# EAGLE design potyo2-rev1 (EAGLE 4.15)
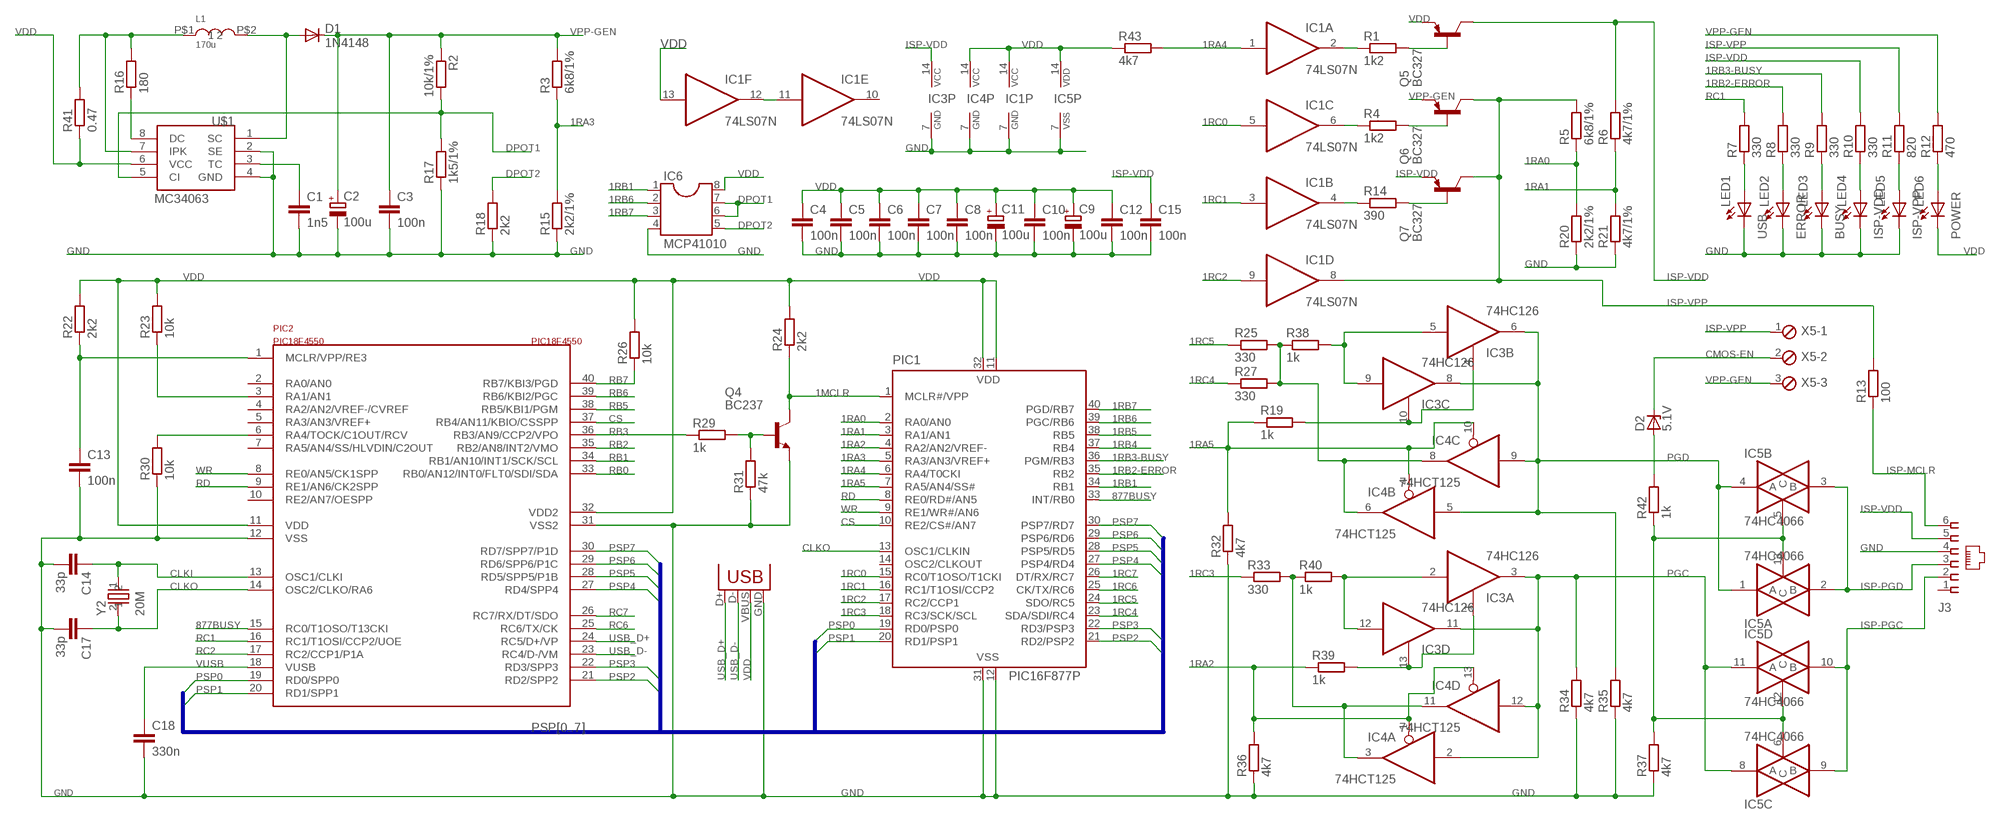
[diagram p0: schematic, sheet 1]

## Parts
C1  1n5  C-EU050-024X044  [C050-024X044]
C2  100u  CPOL-EUE2.5-7  [E2,5-7]
C3  100n  C-EU050-024X044  [C050-024X044]
C4  100n  C-EU050-024X044  [C050-024X044]
C5  100n  C-EU050-024X044  [C050-024X044]
C6  100n  C-EU050-024X044  [C050-024X044]
C7  100n  C-EU050-024X044  [C050-024X044]
C8  100n  C-EU050-024X044  [C050-024X044]
C9  100u  CPOL-EUE2.5-7  [E2,5-7]
C10  100n  C-EU050-024X044  [C050-024X044]
C11  100u  CPOL-EUE2.5-7  [E2,5-7]
C12  100n  C-EU050-024X044  [C050-024X044]
C13  100n  C-EU050-024X044  [C050-024X044]
C14  33p  C-EU050-024X044  [C050-024X044]
C15  100n  C-EU050-024X044  [C050-024X044]
C17  33p  C-EU050-024X044  [C050-024X044]
C18  330n  C-EU050-024X044  [C050-024X044]
D1  1N4148  1N4148DO35-7  [DO35-7]
D2  5.1V  ZENER-DIODEDO34-7  [DO34Z7]
IC1  74LS07N  [DIL14]
IC3  74HC126  74HC126N  [DIL14]
IC4  74HCT125  74HC125N  [DIL14]
IC5  74HC4066  4066N  [DIL14]
IC6  MCP41010  DIL8  [DIL08]
J3  520250-3  [520250-3]
L1  170u  RFB0810  [RFB0810]
LED1  USB  LED5MM  [LED5MM]
LED2  ERROR  LED5MM  [LED5MM]
LED3  BUSY  LED5MM  [LED5MM]
LED4  ISP-VDD  LED5MM  [LED5MM]
LED5  ISP-VPP  LED5MM  [LED5MM]
LED6  POWER  LED5MM  [LED5MM]
PIC1  PIC16F877P  PIC16F8777P  [DIL40]
PIC2  PIC18F4550  [PDIP-40]
Q4  BC237  BC337  [TO92]
Q5  BC327  [TO92-EBC]
Q6  BC327  [TO92-EBC]
Q7  BC327  [TO92-EBC]
R1  1k2  R-EU_0207/10  [0207/10]
R2  10k/1%  R-EU_0207/10  [0207/10]
R3  6k8/1%  R-EU_0207/10  [0207/10]
R4  1k2  R-EU_0207/10  [0207/10]
R5  6k8/1%  R-EU_0207/10  [0207/10]
R6  4k7/1%  R-EU_0207/10  [0207/10]
R7  330  R-EU_0207/10  [0207/10]
R8  330  R-EU_0207/10  [0207/10]
R9  330  R-EU_0207/10  [0207/10]
R10  330  R-EU_0207/10  [0207/10]
R11  820  R-EU_0207/10  [0207/10]
R12  470  R-EU_0207/10  [0207/10]
R13  100  R-EU_0207/10  [0207/10]
R14  390  R-EU_0207/10  [0207/10]
R15  2k2/1%  R-EU_0207/10  [0207/10]
R16  180  R-EU_0207/10  [0207/10]
R17  1k5/1%  R-EU_0207/10  [0207/10]
R18  2k2  R-EU_0207/10  [0207/10]
R19  1k  R-EU_0207/10  [0207/10]
R20  2k2/1%  R-EU_0207/10  [0207/10]
R21  4k7/1%  R-EU_0207/10  [0207/10]
R22  2k2  R-EU_0207/10  [0207/10]
R23  10k  R-EU_0207/10  [0207/10]
R24  2k2  R-EU_0207/10  [0207/10]
R25  330  R-EU_0207/10  [0207/10]
R26  10k  R-EU_0207/10  [0207/10]
R27  330  R-EU_0207/10  [0207/10]
R29  1k  R-EU_0207/10  [0207/10]
R30  10k  R-EU_0207/10  [0207/10]
R31  47k  R-EU_0207/10  [0207/10]
R32  4k7  R-EU_0207/10  [0207/10]
R33  330  R-EU_0207/10  [0207/10]
R34  4k7  R-EU_0207/10  [0207/10]
R35  4k7  R-EU_0207/10  [0207/10]
R36  4k7  R-EU_0207/10  [0207/10]
R37  4k7  R-EU_0207/10  [0207/10]
R38  1k  R-EU_0207/10  [0207/10]
R39  1k  R-EU_0207/10  [0207/10]
R40  1k  R-EU_0207/10  [0207/10]
R41  0.47  R-EU_0207/10  [0207/10]
R42  1k  R-EU_0207/10  [0207/10]
R43  4k7  R-EU_0207/10  [0207/10]
U$1  MC34063  [DIL08]
X1  USB-B-H  [USB-B-H]
X5  MPT3  [3POL254]
Y2  20M  QUARTZ  [QUARTZ]

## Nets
1MCLR: PIC1.1(MCLR#/VPP) Q4.3(C) R24.1
1RA0: PIC1.2(RA0/AN0) R5.1 R20.2
1RA1: PIC1.3(RA1/AN1) R6.1 R21.2
1RA2: IC4.1(A:OE) IC4.13(D:OE) PIC1.4(RA2/AN2/VREF-) R36.2 R39.1
1RA3: PIC1.5(RA3/AN3/VREF+) R3.1 R15.2
1RA4: IC1.1(A:I) PIC1.6(RA4/T0CKI) R43.2
1RA5: IC4.4(B:OE) IC4.10(C:OE) PIC1.7(RA5/AN4/SS#) R19.1 R32.2
1RB1: IC6.1 PIC1.34(RB1)
1RB2-ERROR: PIC1.35(RB2) R8.2
1RB3-BUSY: PIC1.36(PGM/RB3) R9.2
1RB4: PIC1.37(RB4)
1RB5: PIC1.38(RB5)
1RB6: IC6.2 PIC1.39(PGC/RB6)
1RB7: IC6.3 PIC1.40(PGD/RB7)
1RC0: IC1.5(C:I) PIC1.15(RC0/T1OSO/T1CKI)
1RC1: IC1.3(B:I) PIC1.16(RC1/T1OSI/CCP2)
1RC2: IC1.9(D:I) PIC1.17(RC2/CCP1)
1RC3: PIC1.18(RC3/SCK/SCL) R33.1
1RC4: PIC1.23(SDA/SDI/RC4) R27.1
1RC5: PIC1.24(SDO/RC5) R25.1
1RC6: PIC1.25(CK/TX/RC6)
1RC7: PIC1.26(DT/RX/RC7)
877BUSY: PIC1.33(INT/RB0) PIC2.15(RC0/T1OSO/T13CKI)
CLKI: C14.1 PIC2.13(OSC1/CLKI) Y2.1
CLKO: C17.1 PIC1.13(OSC1/CLKIN) PIC2.14(OSC2/CLKO/RA6) Y2.2
CMOS-EN: D2.C X5.2
CMOS-EN2: IC5.5(B:C) IC5.6(C:C) IC5.12(D:C) IC5.13(A:C) R37.2 R42.1
CS: PIC1.10(RE2/CS#/AN7) PIC2.37(RB4/AN11/KBIO/CSSPP)
DPOT1: IC6.6 IC6.7 R2.2 R17.2 U$1.5(CI)
DPOT2: IC6.5 R18.2
GND: C1.2 C2.- C3.2 C4.2 C5.2 C6.2 C7.2 C8.2 C9.- C10.2 C11.- C12.2 C13.2 C14.2 C15.2 C17.2 C18.2 IC1.7(P:GND) IC3.7(P:GND) IC4.7(P:GND) IC5.7(P:VSS) IC6.4 J3.4 LED1.K(C) LED2.K(C) LED3.K(C) LED4.K(C) LED5.K(C) PIC1.12(VSS) PIC1.31(VSS) PIC2.12(VSS) PIC2.31(VSS2) Q4.1(E) R15.1 R17.1 R18.1 R20.1 R21.1 R30.1 R31.1 R32.1 R34.1 R35.1 R36.1 R37.1 U$1.2(SE) U$1.4(GND) X1.GND
ISP-MCLR: J3.6 R13.1
ISP-PGC: IC5.9(C:B) IC5.10(D:B) J3.2
ISP-PGD: IC5.2(A:B) IC5.3(B:B) J3.3
ISP-VDD: C15.1 IC3.14(P:VCC) J3.5 Q5.C Q7.E R6.2 R10.2
ISP-VPP: IC1.8(D:O) Q6.C Q7.C R5.2 R11.2 R13.2 X5.1
MCLR: C13.1 PIC2.1(MCLR/VPP/RE3) R22.1
N$1: IC3.4(B:OE) IC3.10(C:OE) R19.2
N$2: IC3.5(B:I) IC3.9(C:I) R38.2
N$3: R16.1 U$1.8(DC)
N$4: D2.A R42.2
N$5: LED1.A R7.1
N$8: PIC2.6(RA4/TOCK/C1OUT/RCV) R30.2
N$9: PIC2.3(RA1/AN1) R23.1
N$10: Q4.2(B) R29.2 R31.2
N$12: D1.A L1.P$2 U$1.1(SC)
N$13: LED2.A R8.1
N$14: LED3.A R9.1
N$15: IC1.2(A:O) R1.1
N$16: IC1.6(C:O) R4.1
N$17: IC1.4(B:O) R14.1
N$18: Q5.B R1.2
N$19: Q6.B R4.2
N$20: IC3.2(A:I) IC3.12(D:I) R40.2
N$21: Q7.B R14.2
N$22: IC4.6(B:O) IC4.8(C:O) R25.2 R27.2 R38.1
N$23: IC3.1(A:OE) IC3.13(D:OE) R39.2
N$24: C1.1 U$1.3(TC)
N$25: L1.P$1 R16.2 R41.2 U$1.7(IPK)
N$27: LED4.A R10.1
N$28: IC4.3(A:O) IC4.11(D:O) R33.2 R40.1
N$29: LED5.A R11.1
N$30: LED6.A R12.1
N$31: IC1.11(E:I) IC1.12(F:O)
PGC: IC3.3(A:O) IC3.11(D:O) IC4.2(A:I) IC4.12(D:I) IC5.8(C:A) IC5.11(D:A) R34.2
PGD: IC3.6(B:O) IC3.8(C:O) IC4.5(B:I) IC4.9(C:I) IC5.1(A:A) IC5.4(B:A) R35.2
PSP0: PIC1.19(RD0/PSP0) PIC2.19(RD0/SPP0)
PSP1: PIC1.20(RD1/PSP1) PIC2.20(RD1/SPP1)
PSP2: PIC1.21(RD2/PSP2) PIC2.21(RD2/SPP2)
PSP3: PIC1.22(RD3/PSP3) PIC2.22(RD3/SPP3)
PSP4: PIC1.27(PSP4/RD4) PIC2.27(RD4/SPP4)
PSP5: PIC1.28(PSP5/RD5) PIC2.28(RD5/SPP5/P1B)
PSP6: PIC1.29(PSP6/RD6) PIC2.29(RD6/SPP6/P1C)
PSP7: PIC1.30(PSP7/RD7) PIC2.30(RD7/SPP7/P1D)
RB0: PIC2.33(RB0/AN12/INT0/FLT0/SDI/SDA)
RB1: PIC2.34(RB1/AN10/INT1/SCK/SCL)
RB2: PIC2.35(RB2/AN8/INT2/VMO)
RB3: PIC2.36(RB3/AN9/CCP2/VPO) R29.1
RB5: PIC2.38(RB5/KBI1/PGM)
RB6: PIC2.39(RB6/KBI2/PGC)
RB7: PIC2.40(RB7/KBI3/PGD) R26.1
RC1: PIC2.16(RC1/T1OSI/CCP2/UOE) R7.2
RC2: PIC2.17(RC2/CCP1/P1A)
RC6: PIC2.25(RC6/TX/CK)
RC7: PIC2.26(RC7/RX/DT/SDO)
RD: PIC1.8(RE0/RD#/AN5) PIC2.9(RE1/AN6/CK2SPP)
USB_D+: PIC2.24(RC5/D+/VP) X1.D+
USB_D-: PIC2.23(RC4/D-/VM) X1.D-
VDD: C4.1 C5.1 C6.1 C7.1 C8.1 C9.+ C10.1 C11.+ C12.1 IC1.13(F:I) IC1.14(P:VCC) IC4.14(P:VCC) IC5.14(P:VDD) IC6.8 LED6.K(C) PIC1.11(VDD) PIC1.32(VDD) PIC2.11(VDD) PIC2.32(VDD2) Q5.E R22.2 R23.2 R24.2 R26.2 R41.1 R43.1 U$1.6(VCC) X1.VBUS
VPP-GEN: C2.+ C3.1 D1.C Q6.E R2.1 R3.2 R12.2 X5.3
VUSB: C18.1 PIC2.18(VUSB)
WR: PIC1.9(RE1/WR#/AN6) PIC2.8(RE0/AN5/CK1SPP)
Unconnected: IC1.10(E:O) J3.1 PIC1.14(OSC2/CLKOUT) PIC2.2(RA0/AN0) PIC2.4(RA2/AN2/VREF-/CVREF) PIC2.5(RA3/AN3/VREF+) PIC2.7(RA5/AN4/SS/HLVDIN/C2OUT) PIC2.10(RE2/AN7/OESPP)

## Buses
PSP[0..7]

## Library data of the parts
C1 C3-C8 C10 C12-C15 C17 C18 = sajat:C-EU: CAPACITOR, European symbol
C2 C9 C11 = sajat:CPOL-EU: POLARIZED CAPACITOR, European symbol
D1 = sajat:1N4148: DIODE
D2 = diode:ZENER-DIODE: Z-Diode
IC1 = sajat:74*07: Hex BUFFER, open collector high-voltage output
IC3 = sajat:74*126: Quad bus BUFFER, 3-state
IC4 = sajat:74*125: Quad bus BUFFER, 3-state
IC5 = sajat:4066: Quad bilateral ANALOG SWITCH
IC6 = ic-package:DIL8: Dual In Line
J3 = sajat:520250-3: AMP connector
L1 = sajat:RFB0810
LED1-LED6 = sajat:LED: LED
PIC1 = sajat:PIC16F877: MICROCONTROLLER
PIC2 = pic18f4550:PIC18F4550
Q4 = sajat:BC337*: NPN Transistor
Q5-Q7 = sajat:BC327*: PNP Transistror
R1-R27 R29-R43 = sajat:R-EU_: RESISTOR, European symbol
U$1 = sajat:MC34063
X1 = sajat:USB: USB Connectors
X5 = sajat:MPT3: PHOENIX CONNECTOR
Y2 = sajat:QUARTZ

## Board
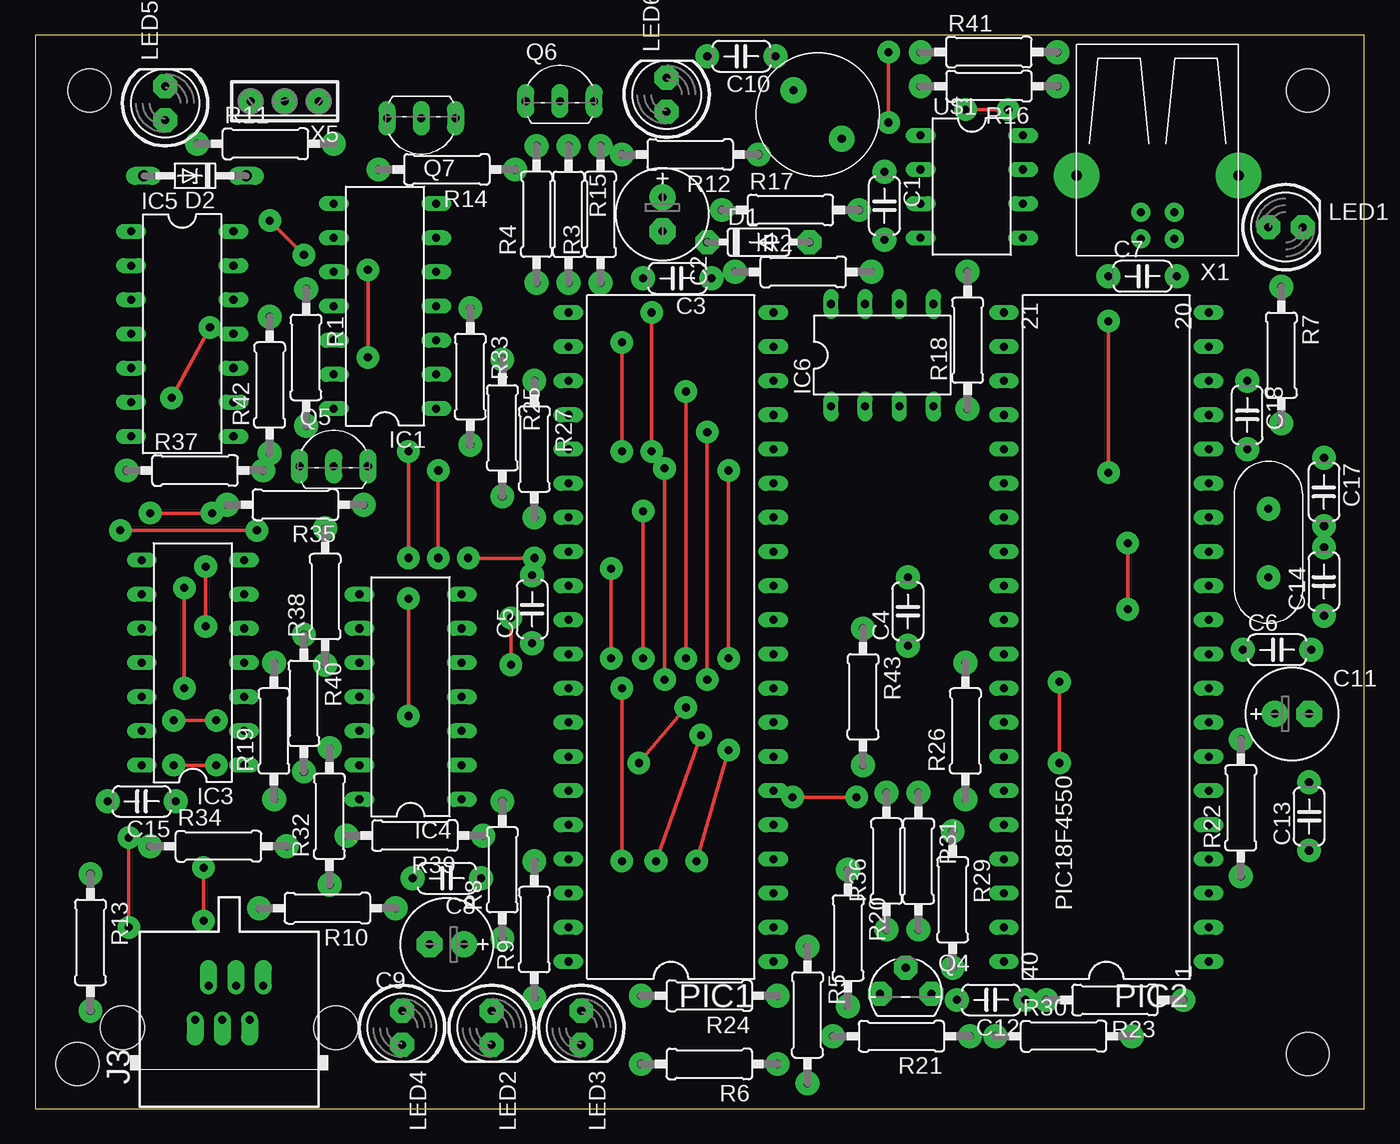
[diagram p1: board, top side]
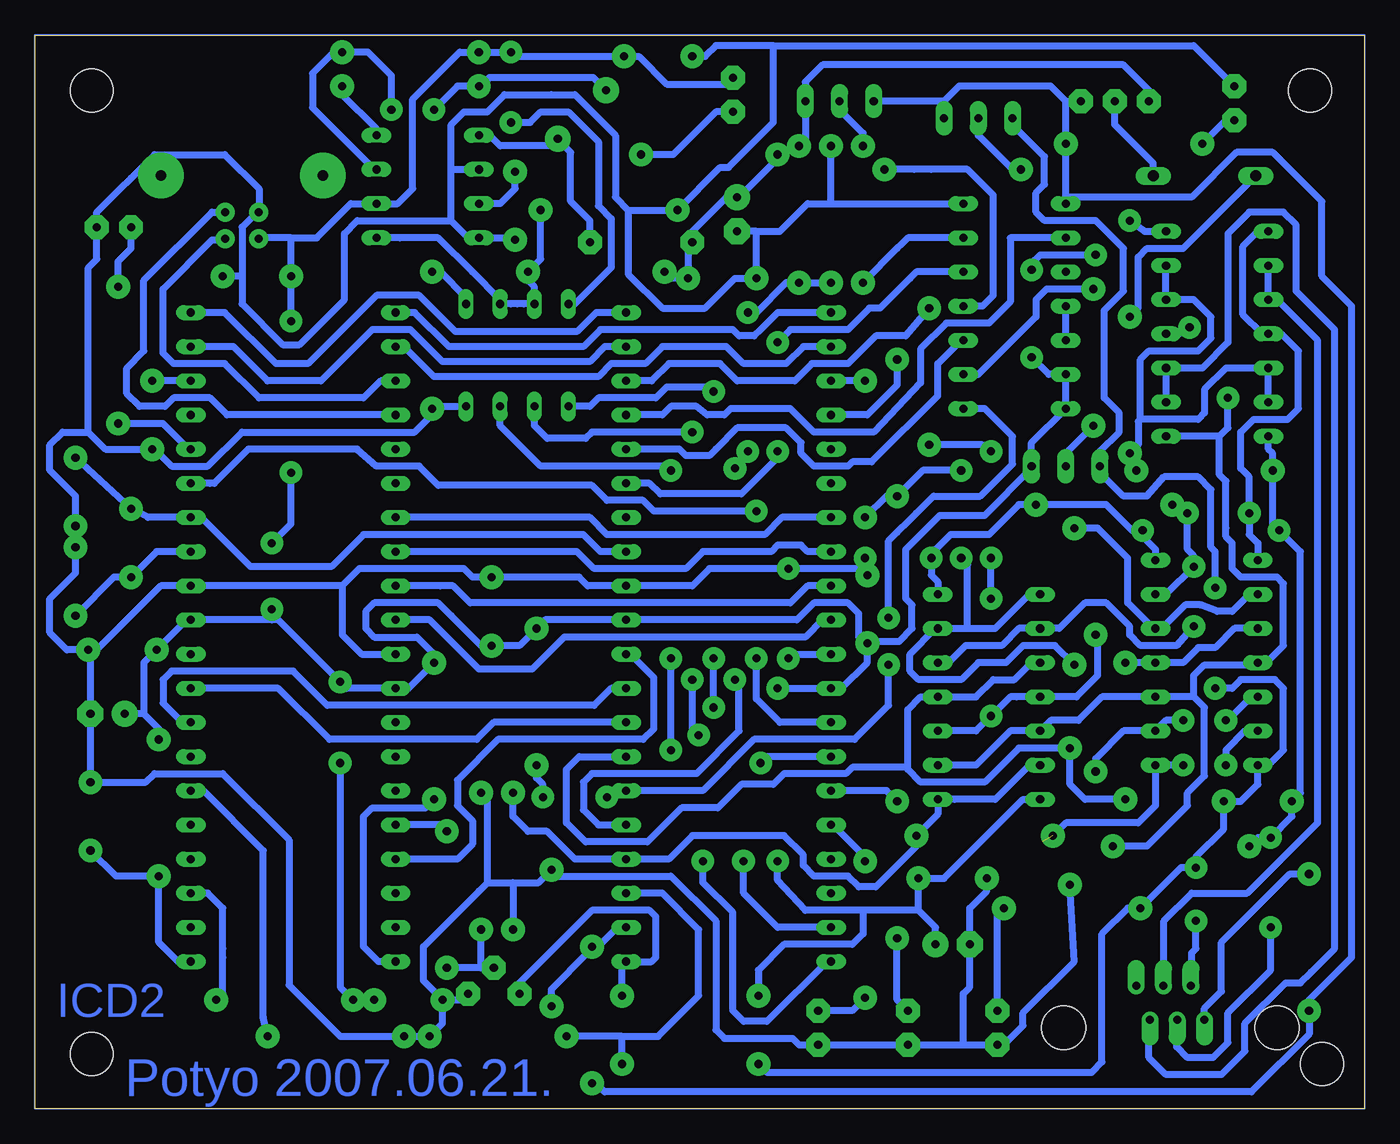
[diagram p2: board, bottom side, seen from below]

Size 98.88 x 79.84 mm. Coordinates in mm from the lower left corner, seen from the top.
Outline: 0,0 98.88,0 98.88,79.84 0,79.84 0,0
Copper layers (1*16): Top 0.035mm / dielectric 1.5mm / Bottom 0.035mm
Design rules "default": minimum track width 20mil, minimum drill 10mil, track to track 10mil, track to pad 10mil, pad to pad 10mil, via to via 10mil, smd to smd 8mil, copper to edge 10mil, drill to drill 15mil, minimum pad ring 10mil, minimum via ring 8mil, stop-mask expansion 4mil, vias tented up to drill 0mil, thermal gap 10mil
Holes 3.2 mm at 4.06,75.72 94.67,75.72 94.67,4.06 3.17,3.33

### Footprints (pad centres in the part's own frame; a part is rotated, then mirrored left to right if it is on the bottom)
C050-024X044 = drill 0.6 pad 1.778 round: 1 -2.54,0; 2 2.54,0
E2,5-7 = drill 0.6 pad 1.93 round: + -1.27,0 | drill 0.6 pad 1.93 octagon: - 1.27,0
DO35-7 = drill 0.6 pad 1.778 octagon: A 3.81,0; C -3.81,0
DO34Z7 = drill 0.813 long: A 3.81,0; C -3.81,0
DIL14 = drill 0.6 pad 1.016 long: 1 -7.62,-3.81; 2 -5.08,-3.81; 3 -2.54,-3.81; 4 0,-3.81; 5 2.54,-3.81; 6 5.08,-3.81; 7 7.62,-3.81; 8 7.62,3.81; 9 5.08,3.81; 10 2.54,3.81; 11 0,3.81; 12 -2.54,3.81; 13 -5.08,3.81; 14 -7.62,3.81
DIL08 = drill 0.6 pad 1.016 long: 1 -3.81,-3.81; 2 -1.27,-3.81; 3 1.27,-3.81; 4 3.81,-3.81; 5 3.81,3.81; 6 1.27,3.81; 7 -1.27,3.81; 8 -3.81,3.81
520250-3 = drill 0.6 pad 1.27 offset: 1 2.54,3.118; 2 1.524,0.578; 3 0.508,3.118; 4 -0.508,0.578; 5 -1.524,3.118; 6 -2.54,0.578 | hole 3.251: -7.938,0; 7.938,0
RFB0810 = drill 0.6 pad 1.93 round: P$1 -2.54,0; P$2 2.54,0
LED5MM = drill 0.6 pad 1.778 octagon: A -1.27,0; K 1.27,0
DIL40 = drill 0.6 pad 1.016 long: 1 -24.13,-7.62; 2 -21.59,-7.62; 3 -19.05,-7.62; 4 -16.51,-7.62; 5 -13.97,-7.62; 6 -11.43,-7.62; 7 -8.89,-7.62; 8 -6.35,-7.62; 9 -3.81,-7.62; 10 -1.27,-7.62; 11 1.27,-7.62; 12 3.81,-7.62; 13 6.35,-7.62; 14 8.89,-7.62; 15 11.43,-7.62; 16 13.97,-7.62; 17 16.51,-7.62; 18 19.05,-7.62; 19 21.59,-7.62; 20 24.13,-7.62; 21 24.13,7.62; 22 21.59,7.62; 23 19.05,7.62; 24 16.51,7.62; 25 13.97,7.62; 26 11.43,7.62; 27 8.89,7.62; 28 6.35,7.62; 29 3.81,7.62; 30 1.27,7.62; 31 -1.27,7.62; 32 -3.81,7.62; 33 -6.35,7.62; 34 -8.89,7.62; 35 -11.43,7.62; 36 -13.97,7.62; 37 -16.51,7.62; 38 -19.05,7.62; 39 -21.59,7.62; 40 -24.13,7.62
PDIP-40 = drill 0.6 pad 1.016 long: 1 -19.05,-8.89; 2 -16.51,-8.89; 3 -13.97,-8.89; 4 -11.43,-8.89; 5 -8.89,-8.89; 6 -6.35,-8.89; 7 -3.81,-8.89; 8 -1.27,-8.89; 9 1.27,-8.89; 10 3.81,-8.89; 11 6.35,-8.89; 12 8.89,-8.89; 13 11.43,-8.89; 14 13.97,-8.89; 15 16.51,-8.89; 16 19.05,-8.89; 17 21.59,-8.89; 18 24.13,-8.89; 19 26.67,-8.89; 20 29.21,-8.89; 21 29.21,6.35; 22 26.67,6.35; 23 24.13,6.35; 24 21.59,6.35; 25 19.05,6.35; 26 16.51,6.35; 27 13.97,6.35; 28 11.43,6.35; 29 8.89,6.35; 30 6.35,6.35; 31 3.81,6.35; 32 1.27,6.35; 33 -1.27,6.35; 34 -3.81,6.35; 35 -6.35,6.35; 36 -8.89,6.35; 37 -11.43,6.35; 38 -13.97,6.35; 39 -16.51,6.35; 40 -19.05,6.35
TO92 = drill 0.6 pad 1.778 octagon: 1 1.905,0; 2 0,1.905; 3 -1.905,0
TO92-EBC = drill 0.6 pad 1.27 long: B 0,-1.27; C -2.54,-1.27; E 2.54,-1.27
0207/10 = drill 0.6 pad 1.778 round: 1 -5.08,0; 2 5.08,0
USB-B-H = drill 0.6 pad 1.422 round: D+ 0,1.25; D- 1.981,1.25; GND 0,-1.25; VBUS 1.981,-1.25 | drill 0.8 pad 3.4 round: P$1 -2.718,-6.02; P$2 -2.718,6.02
3POL254 = drill 0.6 pad 1.778 octagon: 1 -2.54,0; 2 0,0; 3 2.54,0
QUARTZ = drill 0.6 pad 1.778 round: 1 -2.54,0; 2 2.54,0

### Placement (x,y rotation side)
C1  63.18,67.15 270 top
C2  46.67,66.51 270 top
C3  47.78,61.75 180 top
C4  64.92,36.98 90 top
C5  36.98,37.14 90 top
C6  92.39,34.12 0 top
C7  82.39,61.91 0 top
C8  30.63,17.14 180 top
C9  30.63,12.22 180 top
C10  52.54,78.26 180 top
C11  93.5,29.36 0 top
C12  71.12,8.09 180 top
C13  94.77,21.74 90 top
C14  95.88,39.2 90 top
C15  7.93,22.85 180 top
C17  95.88,45.87 270 top
C18  90.16,51.59 270 top
D1  53.81,64.45 0 top
D2  11.9,69.37 180 top
IC1  26.03,59.68 90 top
IC3  11.74,33.17 90 top
IC4  27.93,30.63 90 top
IC5  10.95,57.62 270 top
IC6  63.02,56.03 0 top
J3  14.44,6.03 0 top
L1  58.21,73.92 315 top
LED1  93.02,65.56 0 top
LED2  33.97,6.03 270 top
LED3  40.63,6.03 270 top
LED4  27.3,6.03 270 top
LED5  9.68,74.77 90 top
LED6  46.99,75.4 90 top
PIC1  47.3,35.08 90 top
PIC2  78.42,30 90 top
Q4  64.77,8.57 0 top
Q5  22.22,49.05 0 top
Q6  39.05,76.19 0 top
Q7  28.73,72.38 180 top
R1  20.16,55.87 270 top
R2  57.15,62.22 0 top
R3  42.06,66.51 90 top
R4  37.3,66.51 90 top
R5  57.46,6.98 270 top
R6  50.16,3.33 180 top
R7  92.7,56.03 270 top
R8  34.76,17.77 90 top
R9  37.14,13.33 90 top
R10  21.74,14.92 180 top
R11  17.14,71.75 0 top
R12  48.73,70.95 180 top
R13  4.12,12.38 270 top
R14  30.63,69.84 180 top
R15  39.68,66.51 270 top
R16  70.96,76.04 180 top
R17  56.19,66.83 0 top
R18  69.37,57.14 90 top
R19  17.77,28.09 90 top
R20  60.48,12.69 270 top
R21  64.45,5.39 180 top
R22  89.69,22.38 90 top
R23  80.32,8.09 180 top
R24  50.16,8.41 180 top
R25  34.76,50.63 270 top
R26  69.21,28.09 90 top
R27  37.14,49.05 270 top
R29  68.26,15.55 270 top
R30  76.51,5.39 0 top
R31  65.72,18.41 270 top
R32  21.9,21.74 90 top
R33  32.38,54.44 270 top
R34  13.65,19.52 0 top
R35  19.36,44.92 180 top
R36  63.34,18.41 90 top
R37  11.9,47.46 0 top
R38  21.59,38.09 90 top
R39  28.25,20.31 180 top
R40  20,30.16 270 top
R41  70.96,78.57 0 top
R42  17.46,53.81 90 top
R43  61.59,30.63 270 top
U$1  69.69,68.57 270 top
X1  83.5,66.67 270 top
X5  18.57,74.92 180 top
Y2  91.75,42.06 90 top

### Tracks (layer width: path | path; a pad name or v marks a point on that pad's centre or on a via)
1MCLR
  Bottom 0.508: PIC1.1 55.24,10.63 R24.1 | R24.1 | PIC1.1 | PIC1.1 53.02,10.95 52.7,11.26 52.7,14.28 53.18,14.76 57.46,14.76 62.86,9.36 Q4.3 | Q4.3
1RA0
  Bottom 0.508: 57.46,11.58 | 57.46,11.58 R5.1 | PIC1.2 55.56,13.49 57.46,11.58 | R20.2 60.48,8.88 57.78,11.58 57.46,11.58
1RA1
  Bottom 0.508: PIC1.3 52.22,16.03 49.52,13.33 49.52,8.41 52.54,5.39 55.4,5.39 | R6.1 | 55.24,5.39 55.4,5.39 | 55.4,5.39 R21.2 | R6.1 55.24,5.39 | 55.24,5.39 | 55.4,5.39
1RA2
  Bottom 0.508: IC4.13 24.92,25.55 27.46,23.01 | 27.46,23.01 30.47,23.01 | 30.47,23.01 IC4.1 | IC4.13 | 27.46,23.01 | 30.47,23.01 | IC4.1 | R36.2 | R36.2 63.34,21.74 62.22,20.63 60.8,20.63 58.73,18.57 PIC1.4 51.75,18.57 50,20.31 43.17,20.31 41.75,18.88 41.75,18.09 40.95,17.3 38.41,17.3 37.62,16.5 36.35,16.5 33.33,19.52 R39.1 | R39.1 | IC4.1 31.74,21.9 R39.1
1RA3  (via drill 0.6 pad 1.68)
  Top 0.254: v45.87,48.89 v45.87,59.21 | v46.83,31.9 v46.83,47.62
  Bottom 0.508: PIC1.5 56.99,21.11 58.1,22.22 58.1,24.28 57.46,24.92 53.02,24.92 | v46.83,31.9 46.51,31.58 46.51,28.09 49.68,24.92 53.02,24.92 | R15.2 | R15.2 R3.1 43.02,61.43 45.24,59.21 | 53.02,24.92 | 45.24,59.21 | v45.87,59.21 45.24,59.21 | v46.83,47.62 46.83,47.3 | v46.83,47.62 | v45.87,48.89 45.87,48.57 v46.83,47.62
1RA4  (via drill 0.6 pad 1.68)
  Top 0.254: v35.4,33.01 v35.4,36.51 | v56.35,23.17 v61.11,23.17
  Bottom 0.508: v35.4,36.51 35.4,36.66 35.4,42.22 34.76,42.86 33.81,43.81 33.33,44.28 | IC1.1 | IC1.1 28.25,52.06 26.19,50 26.19,47.94 28.57,45.55 32.06,45.55 33.33,44.28 | 33.33,44.28 | v35.4,33.01 35.4,30 37.94,27.46 45.4,27.46 49.21,23.65 49.52,23.65 PIC1.6 v56.35,23.17 | v61.11,23.17 61.11,24.12 61.59,24.6 R43.2 | R43.2
1RA5
  Bottom 0.508: PIC1.7 58.41,26.19 59.37,25.23 59.37,21.27 57.94,19.84 53.33,19.84 50.79,22.38 48.1,22.38 46.35,24.12 43.97,24.12 43.17,24.92 38.57,24.92 38.09,25.39 33.97,25.39 | IC4.10 | IC4.10 24.76,33.17 26.03,31.9 27.62,31.9 28.89,30.63 IC4.4 | IC4.4 | IC4.4 33.01,30.63 33.97,29.68 33.97,25.39 | 33.97,25.39 33.97,25.23 33.01,24.28 28.25,24.28 25.71,26.82 R32.2 | 17.62,23.01 R19.1 20.79,23.01 21.9,24.12 R32.2 | R32.2 | R32.2 | R32.2 | R32.2
1RB1  (via drill 0.6 pad 1.68)
  Top 0.254: v44.92,25.71 v48.41,29.84 | v48.41,33.49 v48.41,53.33
  Bottom 0.508: v48.41,29.84 v48.41,33.49 | IC6.1 57.62,52.22 57.3,52.54 56.99,52.86 52.7,52.86 51.91,53.65 48.73,53.65 v48.41,53.33 | v44.92,25.71 | PIC1.34 44.44,26.19 v44.92,25.71
1RB2-ERROR
  Bottom 0.508: R8.2 35.55,23.65 PIC1.35
1RB3-BUSY
  Bottom 0.508: PIC1.36 39.52,21.11 37.14,18.73 R9.2
1RB6  (via drill 0.6 pad 1.68)
  Top 0.254: v46.19,18.41 v49.52,27.77 | v50,31.9 v50,50.32
  Bottom 0.508: v49.52,27.77 50,28.25 v50,31.9 | v50,50.32 57.46,50.32 57.94,49.84 60.8,49.84 61.75,50.79 IC6.2 | PIC1.39 43.65,13.49 46.19,16.03 v46.19,18.41
1RB7  (via drill 0.6 pad 1.68)
  Top 0.254: v49.21,18.41 v51.59,26.66 | v51.59,33.49 v51.59,47.46
  Bottom 0.508: v51.59,26.66 51.59,26.82 v51.59,33.49 | v51.59,47.46 51.91,47.78 61.27,47.78 64.29,50.79 IC6.3 | PIC1.40 40,10.95 44.44,6.5 46.19,6.5 46.98,7.3 46.98,14.6 49.21,16.82 v49.21,18.41 | v49.21,18.41
1RC0  (via drill 0.6 pad 1.68)
  Top 0.254: v43.65,56.98 v43.65,48.89
  Bottom 0.508: PIC1.15 53.18,46.51 52.38,45.71 46.35,45.71 43.65,48.41 v43.65,48.89 | v43.65,56.98 42.7,57.94 38.41,57.94 36.82,59.52 36.03,59.52 33.81,61.75 | 33.81,61.75 | IC1.5 33.33,62.22 33.81,61.75
1RC1
  Bottom 0.508: IC1.3 30,57.14 31.74,55.4 31.74,53.02 36.67,48.09 38.09,48.09 38.41,47.78 40.95,47.78 41.9,48.73 41.9,49.52 43.02,50.63 46.67,50.63 48.25,49.05 | PIC1.16 50.95,49.05 50.48,48.57 48.73,48.57 48.25,49.05 | 48.25,49.05
1RC2
  Bottom 0.508: IC1.9 | 33.01,56.03 | 33.01,56.03 33.01,55.71 33.01,53.97 36.51,50.32 40.95,50.32 42.7,52.06 47.14,52.06 47.62,51.59 48.89,51.59 49.68,52.22 51.59,52.22 52.22,51.59 PIC1.17 | 33.01,56.03 33.01,56.51 31.11,58.41 27.93,58.41 26.35,60 26.35,64.76 IC1.9
1RC3
  Bottom 0.508: R33.1 34.13,57.46 36.35,57.46 38.41,55.4 41.11,55.4 42.38,54.13 | 42.38,54.13 | 42.38,54.13 46.67,54.13 47.94,55.4 51.75,55.4 53.02,54.13 PIC1.18
1RC4
  Bottom 0.508: R27.1 | R27.1 PIC1.23 | R27.1
1RC5
  Bottom 0.508: R25.1 34.76,53.81 36.98,51.59 PIC1.24
877BUSY  (via drill 0.6 pad 1.68)
  Top 0.254: v45.24,33.49 v45.24,44.44
  Bottom 0.508: PIC1.33 43.49,28.73 45.24,30.47 v45.24,33.49 | PIC2.15 85.88,46.51 85.56,46.51 83.02,49.05 74.92,49.05 73.5,47.78 70.8,47.78 | 70.8,47.78 70.96,47.78 | v45.24,44.44 46.35,44.44 52.86,44.44 53.65,45.24 56.35,45.24 57.46,46.35 68.89,46.35 70.32,47.78 | 70.32,47.78 | 70.32,47.78 70.8,47.78
CLKI
  Bottom 0.508: PIC2.13 89.85,41.43 Y2.1 93.02,39.52 C14.1
CLKO
  Bottom 0.508: PIC2.14 90.48,43.97 Y2.2 C17.1 | PIC1.13 56.83,41.43 58.1,42.7 74.45,42.7 76.83,40.32 82.86,40.32 86.51,43.97 PIC2.14 | PIC2.14
CMOS-EN
  Bottom 0.508: X5.2 18.57,73.18 15.71,70.32 D2.C
CMOS-EN2
  Bottom 0.508: IC5.5 | IC5.5 | IC5.6 IC5.5 | IC5.5 | IC5.12 | IC5.12 | R37.2 | IC5.5 9.36,55.08 | 9.36,55.08 | 9.36,55.08 10.31,55.08 11.9,53.49 11.9,51.75 12.38,51.27 16.66,51.27 | IC5.12 IC5.13 | IC5.12 | R37.2 16.98,48.25 R42.1 16.82,49.36 16.82,51.11 16.66,51.27 | IC5.12 12.69,60.16 11.42,58.89 11.42,57.3 12.38,56.35 16.03,56.35 16.66,55.71 16.66,51.27
CS
  Bottom 0.508: PIC2.37 67.46,18.57 66.35,19.68 66.35,21.42 67.46,22.54 67.46,24.44 64.45,27.46 53.65,27.46 52.86,28.25 52.86,32.06 54.6,33.81 PIC1.10
DPOT1
  Bottom 0.508: 60.8,66.83 R17.2 61.27,63.18 R2.2 | U$1.5 71.75,64.76 68.89,64.76 66.35,62.22 64.29,60.16 IC6.6 | IC6.6 63.49,59.84 63.02,59.84 | IC6.7 62.54,59.84 63.02,59.84 | 63.02,59.84 | 63.02,59.84 | R2.2 | R2.2 62.22,61.59 61.75,61.11 IC6.7 | IC6.7 | IC6.6
DPOT2
  Bottom 0.508: IC6.5 66.83,60.32 68.73,62.22 R18.2 | R18.2
GND  (via drill 0.6 pad 1.68)
  Top 0.254: v6.34,43.01 v16.5,43.01 | v32.22,40.95 v37.14,40.95 | v42.86,40.16 v42.86,33.49 | v6.98,13.49 v6.98,20.16
  Bottom 0.508: PIC2.31 74.61,33.81 76.04,35.24 76.04,38.89 | 97.78,37.93 95.88,39.84 C14.2 C17.2 95.88,45.55 97.78,47.46 97.78,49.36 96.83,50.32 94.93,50.32 | 94.93,50.32 93.66,49.05 C18.2 89.85,48.89 88.74,47.78 86.04,47.78 83.5,50.32 70.64,50.32 69.37,51.59 R18.1 | 94.93,50.32 94.93,62.54 94.29,63.18 LED1.K 94.29,66.67 92.55,68.41 91.75,69.21 90.01,70.95 84.77,70.95 82.23,68.41 82.23,66.67 X1.GND | 83.5,65.56 82.39,66.67 X1.GND | X1.GND | 65.88,16.19 | C6.2 96.51,34.12 97.78,35.39 97.78,37.93 | 76.04,38.89 PIC2.12 89.53,38.89 94.29,34.12 C6.2 | C10.2 49.05,78.26 48.25,79.05 43.97,79.05 | 83.5,65.56 | 83.5,65.56 83.5,61.91 | 76.04,38.89 | 74.77,40.16 76.04,38.89 | 79.21,56.83 80.48,56.83 83.5,59.84 83.5,61.91 | 43.97,79.05 43.97,75.72 43.97,74.92 43.97,73.34 47.3,70 47.94,70 R17.1 | 39.68,67.3 41.43,67.3 43.49,65.24 45.24,65.24 | 39.68,67.3 R15.1 | LED3.K | LED3.K | LED3.K 42.06,4.76 42.54,5.23 47.62,5.23 48.25,5.87 48.25,13.96 51.59,17.3 60,17.3 R20.1 | 33.81,4.76 LED2.K 29.84,4.76 | LED3.K 33.81,4.76 | 33.81,4.76 | 29.84,4.76 29.84,8.57 29.36,9.04 C9.- 29.36,14.92 28.09,16.19 C8.2 | 29.84,4.76 LED4.K 26.82,4.76 25.39,6.18 25.39,7.14 21.58,10.95 R32.1 | C7.2 84.13,61.91 83.5,61.91 | 6.82,45.4 | C2.- | 45.24,65.24 C2.- | 45.24,65.24 C3.2 46.83,61.75 49.05,59.52 52.22,59.52 54.76,62.06 54.76,66.83 | R17.1 | 54.76,66.83 R17.1 | 54.76,66.83 | 54.76,66.83 55.72,67.78 55.72,72.38 58.73,75.4 60.48,75.4 63.97,75.4 65.24,74.13 66.99,74.13 67.94,73.18 67.94,69.84 | C4.2 | C4.2 | C4.2 66.35,39.52 66.99,40.16 74.77,40.16 | 74.77,40.16 | C8.2 | C8.2 27.46,17.14 | 25.08,44.92 | 25.08,44.92 R35.1 25.71,44.92 27.93,42.7 30.79,42.7 32.22,41.27 v32.22,40.95
  Bottom 0.508: 25.08,44.92 19.2,44.92 17.3,43.01 v16.5,43.01 16.5,42.54 15.55,41.59 IC3.7 | 6.82,43.49 4.76,41.43 4.76,23.49 C15.2 5.39,21.74 v6.98,20.15 | 6.82,43.49 6.82,45.4 | v6.34,43.01 6.82,43.49 | v6.98,20.15 | v6.98,20.15 v6.98,20.16 7.93,20.16 R34.1 | R34.1 | v6.98,13.49 6.98,10.31 10.15,7.14 10.15,4.91 11.27,3.8 13.17,3.8 13.96,4.6 13.96,6.03 13.93,6.63 | 13.93,6.63 13.96,6.66 | 13.93,6.63 J3.4 | C1.2 63.34,64.76 64.92,64.76 U$1.4 66.67,64.76 67.94,66.03 | R18.1 | IC6.4 69.21,52.22 R18.1 | 67.94,66.03 74.92,66.03 75.88,65.08 75.88,60.16 79.21,56.83 | 67.94,69.84 U$1.2 | 67.94,66.03 67.94,69.84 | 67.94,69.84 | 97.78,37.93 | C13.2 | C11.- | C11.- C13.2 | C11.- | C11.- 94.77,33.97 C6.2 | 79.21,56.83 | 6.82,48.73 | R37.1 6.82,48.73 | R37.1 | 6.82,45.4 R37.1 | v37.14,40.95 37.14,40.63 37.54,40.24 | 37.54,40.24 37.62,40.16 37.94,40.16 v42.86,40.16 48.73,40.16 50,38.89 PIC1.12 57.78,38.89 58.41,39.52 C4.2 | 37.54,40.24 37.46,40.16 C5.2 | v32.22,40.95 | v32.22,40.95 32.22,39.68 31.74,39.2 | R21.1 | C12.2 68.57,6.34 R21.1 | R21.1 R30.1 76.19,5.39 80,9.2 80,20 84.93,24.92 90.01,24.92 90.64,24.28 C13.2 | PIC1.31 42.54,33.81 v42.86,33.49 | 65.88,16.19 70,12.06 70,9.52 C12.2 | C12.2 | C12.2 | 65.88,16.19 65.24,16.82 | R20.1 | R31.1 65.24,23.01 65.24,16.82 | 65.24,16.82 63.34,16.82 | R20.1 61.43,16.82 63.34,16.82 | R36.1 | R36.1 63.34,16.82 | IC5.7 | 6.82,48.73 7.14,49.05 IC5.7 | IC3.7 | IC4.7 | 31.74,39.2 | 31.74,39.2 IC4.7 | IC1.7 | IC1.7 | 39.68,67.3 IC1.7 | LED5.K | LED5.K | 43.97,79.05 12.69,79.05 LED5.K | C12.2 | C12.2 | Q4.1 67.15,8.09 C12.2
ISP-MCLR
  Bottom 0.508: J3.6 11.9,6.66 11.9,7.45 10.63,8.72 10.63,12.38 5.55,17.46 R13.1
ISP-PGC
  Bottom 0.508: IC5.10 | IC5.10 12.06,55.08 10.15,56.98 10.15,65.08 8.57,66.67 6.03,66.67 5.07,65.72 5.07,60.79 2.22,57.94 2.22,28.57 2.22,11.9 3.17,10.95 3.96,10.15 4.76,9.36 5.87,9.36 8.88,6.34 8.88,4.28 10.63,2.53 14.76,2.53 16.03,3.8 16.03,5.87 J3.2 | IC5.10 IC5.9 | IC5.9
ISP-PGD
  Bottom 0.508: IC5.3 | IC5.3 | IC5.3 6.5,60.16 3.49,57.14 3.49,21.27 8.73,16.03 12.85,16.03 14.92,13.96 14.92,9.68 J3.3 | IC5.2 | IC5.3 IC5.2 | IC5.2
ISP-VDD  (via drill 0.6 pad 1.68)
  Top 0.254: v11.11,31.27 v11.11,38.73 | v12.54,13.96 v12.54,17.93
  Bottom 0.508: IC3.14 | IC3.14 | R6.2 44.44,2.69 22.22,2.69 | 9.2,31.9 9.84,31.27 v11.11,31.27 | IC3.14 7.14,25.55 6.03,26.66 6.03,31.27 6.66,31.9 9.2,31.9 | 9.2,31.9 | 22.22,2.69 | 22.22,2.69 20.31,2.69 19.52,3.49 19.52,13.01 17.62,14.92 R10.2 13.65,17.93 v12.54,17.93 12.54,18.73 10.47,20.79 C15.1 9.2,22.85 7.93,24.12 IC3.14 | v11.11,38.73 | v11.11,38.73 11.11,41.43 11.42,41.74 11.42,46.03 12.38,46.98 14.92,46.98 16.19,45.55 17.93,45.55 18.57,46.19 19.68,47.3 Q5.C 19.68,48.89 18.25,50.32 18.25,51.75 19.36,52.86 19.36,59.37 17.93,60.79 17.93,63.97 20,66.03 20.16,66.03 | 20.16,66.03 23.81,66.03 24.44,66.67 24.44,68.1 23.81,68.73 23.81,70.8 26.19,73.18 Q7.E | v12.54,13.96 12.54,11.9 12.85,11.58 12.85,9.2 J3.5 | 20.16,66.03 20.31,66.03 | Q7.E
ISP-VPP
  Bottom 0.508: R5.2 | R5.2 | R5.2 57.14,1.9 56.51,1.26 8.41,1.26 4.12,5.55 4.12,8.09 | 4.12,8.09 0.95,11.26 0.95,59.68 3.17,61.91 | R13.2 4.12,8.09 | 4.12,8.09 | 3.17,61.91 | 3.17,61.91 | 3.17,61.91 3.17,67.46 6.82,71.11 9.52,71.11 12.85,67.78 22.22,67.78 | Q7.C | 31.27,74.92 Q6.C | 31.27,74.92 Q7.C | 31.27,74.92 | 31.27,74.92 30.16,76.03 23.33,76.03 22.22,74.92 | 22.22,74.92 R11.2 22.22,67.78 | 22.22,74.92 X5.1 | IC1.8 | 22.22,67.78 IC1.8
MCLR
  Bottom 0.508: PIC2.1 88.26,10.95 89.69,12.38 R22.1 | R22.1 | C13.1 | R22.1 92.86,17.3 C13.1
N$1
  Bottom 0.508: IC3.10 9.68,35.71 11.11,34.28 12.38,34.28 13.49,33.17 IC3.4 | IC3.4 | R19.2 17.3,33.17 16.66,33.17 IC3.4
N$2
  Bottom 0.508: IC3.5 15.08,35.71 13.33,37.46 12.22,37.46 10.95,36.98 9.84,36.98 8.57,38.25 IC3.9 | IC3.5 | IC3.5 15.71,35.71 17.62,37.62 17.62,40.95 19.84,43.17 R38.2 | R38.2
N$3
  Bottom 0.508: U$1.8 73.5,72.86 76.04,75.4 R16.1 | R16.1
N$4
  Bottom 0.508: R42.2 16.82,59.52 16.82,63.33 16.19,63.97 13.49,63.97 D2.A
N$5
  Bottom 0.508: R7.1 92.7,63.02 91.75,63.97 LED1.A
N$8
  Bottom 0.508: PIC2.6 86.35,23.65 81.91,19.2 81.91,6.82 R30.2
N$9
  Bottom 0.508: PIC2.3 86.04,16.03 84.93,14.92 84.93,11.9 84.93,11.26 84.93,8.57 R23.1 | R23.1
N$10
  Bottom 0.508: R29.2 | R29.2 | 65.72,10.47 R31.2 | 65.72,10.47 R29.2 | 65.72,10.47 | Q4.2 | Q4.2 65.72,10.47
N$11
  Bottom 0.1: -0.01,79.84 98.9,79.84 98.9,-0.01 -0.01,-0.01 -0.01,79.84
N$12
  Bottom 0.508: D1.A 57.62,66.03 59.05,67.46 59.05,71.11 60,72.07 | U$1.1 65.08,72.38 64.29,71.59 60.48,71.59 60,72.07 | 60,72.07 60.01,72.07 L1.P$2
N$13
  Bottom 0.508: LED2.A 34.76,8.09 R8.1
N$14
  Bottom 0.508: R9.1 38.09,7.3 39.52,7.3 LED3.A | LED3.A | LED3.A
N$15
  Bottom 0.508: R1.1 20.63,60.95 23.65,60.95 24.44,60.16 24.44,58.89 | 24.44,58.89 | IC1.2 | 24.44,58.89 28.73,54.6 IC1.2
N$16
  Bottom 0.508: R4.1 34.76,63.97 34.44,64.29 33.97,64.76 IC1.6
N$17
  Bottom 0.508: IC1.4 28.41,59.68 27.62,60.48 27.62,67.94 29.52,69.84 32.22,69.84 33.49,69.84 R14.1
N$18
  Bottom 0.508: R1.2 20.79,50.16 22.22,48.73 Q5.B | Q5.B
N$19
  Bottom 0.508: Q6.B 39.05,74.29 37.3,72.54 37.3,71.91 R4.2
N$20  (via drill 0.6 pad 1.68)
  Top 0.254: v10.31,28.89 v13.49,28.89
  Bottom 0.508: 8.41,30.63 | 8.41,30.63 IC3.12 | v10.31,28.89 10.15,28.89 8.41,30.63 | IC3.2 | v13.49,28.89 14.76,28.89 IC3.2 | R40.2 20,26.03 17.93,28.09 IC3.2
N$21
  Bottom 0.508: R14.2 | Q7.B 28.73,72.38 26.19,69.84 R14.2 | R14.2 | R14.2
N$22  (via drill 0.6 pad 1.68)
  Top 0.254: v30,40.95 v30,47.46
  Bottom 0.508: R27.2 35.55,45.55 R25.2 | IC4.6 | IC4.8 24.92,38.25 27.46,35.71 29.52,35.71 | IC4.6 29.52,35.71 | v30,40.95 29.52,40.47 29.52,35.71 | R25.2 | v30,47.46 32.86,47.46 R25.2 | 31.9,35.71 | 31.9,35.71 IC4.6 | 31.9,35.71 33.81,33.81 33.81,32.54 33.17,31.9 30,31.9 28.73,33.17 26.66,33.17 25.39,34.44 23.01,34.44 R38.1 | R38.1
N$23  (via drill 0.6 pad 1.68)  (1 unrouted)
  Top 0.254: v10.31,25.55 v13.49,25.55
  Bottom 0.508: v13.49,25.55 14.28,25.55 IC3.1 15.55,22.54 16.82,21.27 22.22,21.27 R39.2 | v10.31,25.55 10.31,26.66 8.88,28.09 IC3.13 | R39.2
N$24
  Bottom 0.508: C1.1 63.18,68.41 64.29,67.3 U$1.3
N$25  (via drill 0.6 pad 1.68)
  Top 0.254: v69.21,74.29 v72.38,74.29
  Bottom 0.508: L1.P$1 57.36,76.67 65.08,76.67 65.72,76.03 R16.2 | R16.2 | R16.2 67.46,76.03 v69.21,74.29 | v72.38,74.29 | v72.38,74.29 72.38,76.83 74.13,78.57 R41.2 76.67,78.57 78.26,76.99 78.26,74.45 73.65,69.84 U$1.7
N$27
  Bottom 0.508: LED4.A | LED4.A | LED4.A | LED4.A | R10.1 27.3,14.44 LED4.A
N$28  (via drill 0.6 pad 1.68)
  Top 0.254: v27.78,40.95 v27.78,48.89 | v27.78,29.2 v27.78,37.93
  Bottom 0.508: IC4.11 25.87,30.63 | R33.2 | R33.2 | v27.78,48.89 28.41,49.36 R33.2 | v27.78,37.93 v27.78,40.95 | 25.87,30.63 | 25.87,30.63 26.35,30.63 v27.78,29.2 28.89,28.09 IC4.3 | R40.1 19.84,34.92 19.84,32.22 21.43,30.63 IC4.11 | IC4.11
N$29
  Bottom 0.508: R11.1 | LED5.A 10.31,73.49 R11.1
N$30
  Bottom 0.508: R12.1 51.43,70.95 48.25,74.13 LED6.A | LED6.A
N$31
  Bottom 0.508: IC1.12 IC1.11
PGC  (via drill 0.6 pad 1.68)
  Top 0.254: v10.15,52.86 v13.01,58.1
  Bottom 0.508: IC4.12 26.35,28.09 28.89,25.55 IC4.2 | IC4.2 | IC4.12 | IC3.11 | IC3.11 7.3,33.17 6.03,34.44 6.03,39.05 6.5,39.52 9.2,39.52 9.84,40.16 9.84,42.06 10.31,42.54 10.31,43.17 10.31,46.67 10.79,47.14 10.79,50 | 12.69,30.63 | 12.69,30.63 IC3.3 | 12.69,30.63 11.9,29.84 11.9,24.76 13.17,23.49 13.17,22.54 16.19,19.52 R34.2 | IC3.11 8.09,33.01 11.9,33.01 12.69,32.22 12.69,30.63 | IC5.8 | 10.79,50 IC5.8 | IC5.11 | v13.01,58.1 13.81,57.62 IC5.11 | IC3.3 | v10.15,52.86 10.15,50.63 10.79,50 | R34.2 | IC3.3 19.52,30.63 21.27,28.89 23.33,28.89 IC4.12 | IC4.12
PGD  (via drill 0.6 pad 1.68)
  Top 0.254: v13.17,44.28 v8.57,44.28 | v12.69,35.87 v12.69,40.32
  Bottom 0.508: IC5.4 | IC5.4 | IC5.4 | IC5.4 6.19,57.62 4.92,56.35 4.92,52.06 5.71,51.27 6.5,51.27 8.25,51.27 9.2,50.32 9.2,48.41 9.2,47.62 8.57,46.98 8.57,45.87 v8.57,44.28 8.57,43.81 8.57,42.7 7.93,42.06 IC3.8 | IC4.9 | IC4.9 25.71,35.71 26.98,34.44 29.68,34.44 30.95,33.17 IC4.5 | IC4.5 | IC4.9 | v12.69,40.32 | IC3.6 14.76,38.25 v12.69,40.32 | IC5.1 7.93,65.24 9.04,64.13 9.04,59.05 7.61,57.62 | 7.61,57.62 | IC5.4 7.61,57.62 | v12.69,35.87 13.96,34.44 14.44,34.44 16.66,34.44 17.46,35.24 17.46,35.87 19.2,37.62 20.79,37.62 22.7,35.71 IC4.9 | IC4.5 | v12.69,40.32 12.69,41.11 13.17,41.59 v13.17,44.28 14.12,44.6 14.44,44.92 | 14.44,44.92 | 14.44,44.92 R35.2 | IC4.9
PSP0
  Bottom 0.508: PIC1.19 56.51,56.67 57.62,55.56 68.57,55.56 70.96,57.94 73.81,57.94 77.62,54.13 81.59,54.13 84.13,56.67 PIC2.19 | PIC2.19 | PIC2.19
PSP1
  Bottom 0.508: PIC1.20 57.14,59.21 58.57,57.78 67.62,57.78 70.32,60.48 73.5,60.48 78.58,55.4 80.96,55.4 84.77,59.21 PIC2.20 | PIC2.20
PSP2
  Bottom 0.508: PIC1.21 43.65,59.21 44.92,57.94 | PIC2.21 70.64,59.21 68.1,56.67 58.1,56.67 56.83,57.94 46.98,57.94 46.51,57.46 45.4,57.46 44.92,57.94 | 44.92,57.94
PSP3
  Bottom 0.508: PIC1.22 41.75,56.67 43.02,55.4 46.19,55.4 47.46,56.67 52.22,56.67 53.49,55.4 56.03,55.4 | PIC2.22 71.43,56.67 69.21,54.44 56.99,54.44 56.03,55.4 | 56.03,55.4
PSP4
  Bottom 0.508: PIC1.27 43.33,43.97 44.6,42.7 56.35,42.7 57.62,43.97 PIC2.27
PSP5
  Bottom 0.508: PIC2.28 65.4,41.43 58.57,41.43 57.3,40.16 50.48,40.16 49.21,41.43 44.13,41.43 43.65,41.9 41.9,41.9 41.43,41.43 PIC1.28
PSP6
  Bottom 0.508: PIC2.29 68.73,38.89 67.78,38.89 66.51,37.62 42.7,37.62 41.43,38.89 PIC1.29
PSP7
  Bottom 0.508: PIC1.30 40.32,36.35 41.59,35.08 59.53,35.08 61.91,32.7 65.88,32.7 69.53,36.35 PIC2.30
RB3
  Bottom 0.508: R29.1 68.73,21.11 PIC2.36 | R29.1
RB7
  Bottom 0.508: PIC2.40 73.34,10.95 74.45,12.06 74.45,21.74 73.81,22.38 69.84,22.38 R26.1
RC1
  Bottom 0.508: PIC2.16 87.47,49.05 89.37,50.95 R7.2
RD
  Bottom 0.508: PIC2.9 80.8,31.27 76.99,27.46 66.03,27.46 64.76,28.73 PIC1.8
USB_D+
  Bottom 0.508: X1.D+ | X1.D+ 85.72,66.67 90.8,61.59 90.8,56.35 92.07,55.08 92.07,53.17 91.12,52.22 89.21,52.22 88.58,52.86 85.88,52.86 84.61,51.59 PIC2.24
USB_D-
  Bottom 0.508: 84.77,55.4 88.58,55.4 89.37,56.19 89.37,60.95 85.72,64.6 84.77,64.6 84.77,64.67 X1.D- | PIC2.23 73.18,54.13 74.45,52.86 82.23,52.86 84.77,55.4 | 84.77,55.4
VDD  (via drill 0.6 pad 1.68)
  Top 0.254: v76.19,31.74 v76.19,25.71 | v43.65,18.41 v43.65,31.27 | v79.85,47.3 v79.85,58.57 | v81.27,37.14 v81.27,42.06 | v63.49,78.57 v63.49,73.34 | v20,63.49 v17.46,66.03 | v24.76,55.87 v24.76,62.38
  Bottom 0.508: 81.27,36.35 PIC2.11 87.62,36.35 C6.1 90.8,33.17 90.8,29.36 | 67.94,36.66 68.89,37.62 73.65,37.62 74.29,36.98 74.29,35.71 73.65,35.08 70.48,35.08 69.21,33.81 R26.2 71.11,31.27 PIC2.32 | v76.19,25.71 76.19,10.63 76.19,9.04 R23.2 73.18,8.09 C12.1 | 81.27,36.35 v81.27,37.14 | 33.17,42.54 34.13,41.59 34.13,37.93 33.65,37.46 33.65,35.71 34.6,34.76 37.3,34.76 | R24.2 | 37.3,34.76 37.62,35.08 37.62,36.66 37.62,36.82 38.41,37.62 40.95,37.62 42.22,36.35 PIC1.11 60.95,36.35 R43.1 | 37.3,34.76 C5.1 36.98,33.17 38.89,31.27 PIC1.32 | 37.3,34.76 | 33.17,42.54 | 33.17,42.54 31.59,44.13 28.25,44.13 24.76,47.62 Q5.E | 67.94,36.66 | 67.94,36.66 65.72,34.44 C4.1 62.86,34.44 R43.1 | IC6.8 58.73,59.84 56.03,62.54 56.03,66.19 56.99,67.14 56.99,71.91 59.21,74.13 61.27,74.13 62.07,73.34 v63.49,73.34 | PIC1.32 | LED6.K | LED6.K 47.46,76.19 51.91,76.19 53.97,78.26 C10.1 | IC4.14 25.39,23.01 31.27,17.14 C8.1 | PIC2.32 | 81.27,36.35 80.8,36.35 v76.19,31.74 | v76.19,31.74 | v76.19,31.74 | PIC2.32 75.72,31.27 v76.19,31.74 | v79.85,58.57 | X1.VBUS 82.17,64.76 79.85,64.76 | v81.27,42.06 | v81.27,42.06 | v79.85,47.3 79.85,43.49 v81.27,42.06 | 79.85,64.76 77.94,64.76 75.4,67.3 U$1.6 | U$1.6 | U$1.6 | C10.1 | v63.49,78.57 | C10.1 63.18,78.26 v63.49,78.57 | v63.49,78.57 R41.1 67.3,78.57 70.8,75.08 70.8,68.41 71.91,67.3 | 71.91,67.3 | U$1.6 71.91,67.3 | v79.85,58.57 C7.1 79.85,64.76 | R22.2 89.69,28.25 90.8,29.36 | C11.+ | 90.8,29.36 C11.+ | IC1.14 24.76,49.52 Q5.E | Q5.E | IC5.14 16.35,65.24 v17.46,66.03 | v20,63.49 24.12,63.49 24.76,62.86 v24.76,62.38 | IC1.13 | v24.76,55.87 23.49,54.6 IC1.13 | IC1.14 | IC1.14 IC1.13 | v43.65,18.41 43.65,16.98 41.59,14.76 37.3,14.76
  Bottom 0.508: C8.1 | 33.17,14.76 37.3,14.76 | 33.17,14.76 C8.1 | C9.+ 31.9,13.49 33.17,14.76 | 37.3,14.76 37.3,13.01 38.09,12.22 43.17,12.22 45.08,10.31 R24.2 | R24.2 | v43.65,31.27 | v43.65,31.27 PIC1.32 | R43.1
VPP-GEN
  Bottom 0.508: Q6.E 41.59,76.35 40.32,77.62 17.93,77.62 16.03,75.72 X5.3 | R3.2 | 50.16,64.45 D1.C | 50.16,64.45 50.16,65.08 47.46,67.78 C2.+ 46.67,67.62 | R2.1 51.59,61.75 C3.1 | C3.1 | 50.16,64.45 50.32,64.29 C3.1 | 46.67,67.62 | 46.67,67.62 43.65,70.64 R12.2 R3.2 | Q6.E 41.59,72.07 R3.2 | Q6.E | R3.2
VUSB
  Bottom 0.508: PIC2.18 C18.1
WR
  Bottom 0.508: PIC2.8 87.94,28.73 89.37,30.16 89.37,31.9 88.74,32.54 79.69,32.54 77.15,30 57.3,30 56.03,31.27 PIC1.9

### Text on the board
Bottom: ICD2 | Potyo 2007.06.21.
